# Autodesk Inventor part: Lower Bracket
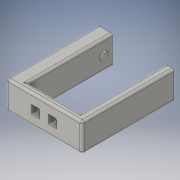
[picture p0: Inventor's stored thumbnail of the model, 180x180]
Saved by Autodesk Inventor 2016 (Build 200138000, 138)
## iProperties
Created: 2015-09
Part Number: Lower Bracket
Material: Generic
Document SubType Name: Modeling
Designer: ChombaW
Density: 1 g/cm^3
Appearance: Default
Author: ChombaW
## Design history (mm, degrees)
sketch "Sketch1"
  geometry: L1 (27.165, 10.16)-(-27.165, 10.16); L2 (-27.165, 10.16)-(-27.165, -10.16); L3 (-27.165, -10.16)-(27.165, -10.16); L4 (27.165, -10.16)-(27.165, 10.16); L5 (27.165, 10.16)-(-27.165, -10.16); L6 (-27.165, 10.16)-(27.165, -10.16); 1 further point
  constraints: 12 end point, 2 midpoint, 2 parallel, 1 horizontal, 1 perpendicular
  dimensions: "d0" = 54.3306 distance of L3.end L2.end; "d1" = 20.32 distance of L2.end L1.end
extrude "Extrusion1" new body sketch "Sketch1" distance "d2" = 5.08; taper "d3" = 0 deg
sketch "Sketch2"
  geometry: L1 (-3.048, 3.048)-(-9.144, 3.048); L2 (-9.144, 3.048)-(-9.144, -3.048); L3 (-9.144, -3.048)-(-3.048, -3.048); L4 (-3.048, -3.048)-(-3.048, 3.048); L5 (-3.048, 3.048)-(-9.144, -3.048); L6 (-9.144, 3.048)-(-3.048, -3.048); L7 (9.144, -3.048)-(3.048, -3.048); L8 (3.048, -3.048)-(3.048, 3.048); L9 (3.048, 3.048)-(9.144, 3.048); L10 (9.144, 3.048)-(9.144, -3.048); L11 (9.144, -3.048)-(3.048, 3.048); L12 (3.048, -3.048)-(9.144, 3.048); L13 (27.165, -10.16)-(27.165, 10.16) reference; L14 (-27.165, 10.16)-(-27.165, -10.16) reference; 3 further points
  constraints: 24 end point, 4 midpoint, 4 parallel, 2 horizontal, 2 perpendicular
  dimensions: "d4" = 6.096 distance of L3.end L2.end; "d5" = 6.096 distance of L2.end L1.end; "d6" = 6.096 distance of L8.end L9.end; "d7" = 6.096 distance of L7.end L8.end; "d8" = 12.192 distance of L8.end L1.end; "d9" = 18.0213 distance from line of L13 L9.end; "d10" = 18.0213 distance from line of L14 L2.end
extrude "Extrusion2" cut sketch "Sketch2" distance "d11" = 5.08; taper "d12" = 0 deg
sketch "Sketch3"
  geometry: L1 (27.165, 10.16)-(16.65, 10.16); L2 (16.65, 10.16)-(16.65, -10.16); L3 (16.65, -10.16)-(27.165, -10.16); L4 (27.165, -10.16)-(27.165, 10.16); L5 (27.165, 10.16)-(16.65, -10.16); L6 (16.65, 10.16)-(27.165, -10.16); L7 (27.165, -10.16)-(27.165, 10.16) reference; L8 (-21.069, 10.16)-(-27.165, 10.16); L9 (-27.165, 10.16)-(-27.165, -10.16); L10 (-27.165, -10.16)-(-21.069, -10.16); L11 (-21.069, -10.16)-(-21.069, 10.16); L12 (-21.069, 10.16)-(-27.165, -10.16); L13 (-27.165, 10.16)-(-21.069, -10.16); L14 (-27.165, 10.16)-(-27.165, -10.16) reference; 3 further points
  constraints: 24 end point, 4 midpoint, 4 parallel, 2 horizontal, 2 perpendicular
  dimensions: "d13" = 10.5156 distance of L3.end L2.end; "d14" = 20.32 distance of L2.end L1.end; "d15" = 0 distance from line of L7 L1.start; "d16" = 6.096 distance of L10.end L9.end; "d17" = 20.32 distance of L9.end L8.end; "d18" = 0 distance from line of L14 L8.end
extrude "Extrusion3" join sketch "Sketch3" distance "d19" = 60.4266; taper "d20" = 0 deg
sketch "Sketch4"
  geometry: L1 (-51.51, 14.427)-(-40.457, 14.427); L2 (-40.457, 14.427)-(-27.428, 12.82); L3 (-27.428, 7.5)-(-40.457, 5.893); L4 (-40.457, 5.893)-(-53.372, 5.439); L5 (-53.372, 5.439)-(-65.507, 5.439); L6 (-65.507, 0)-(-65.507, 20.32) reference; L7 (-53.372, 14.881)-(-65.507, 14.881); A1 r 4.724 centre (-53.538, 10.16) between (-51.51, 14.427) and (-53.372, 5.439); A2 r 4.267 centre (-40.457, 10.16) between (-40.457, 14.427) and (-40.457, 5.893); A3 r 2.68 centre (-27.757, 10.16) between (-27.428, 12.82) and (-27.428, 7.5); 1 further point
  constraints: 12 end point, 7 point on circle, 3 centre point, 3 tangent, 2 point on line, 1 horizontal, 1 parallel
  dimensions: "d21" = 9.4488 diameter of A1; "d22" = 8.5344 diameter of A2; "d23" = 5.3594 diameter of A3; "d24" = 13.081 distance of A2.centre A1.centre; "d25" = 12.7 distance of A3.centre A2.centre
extrude "Extrusion4" cut sketch "Sketch4" distance "d26" = 9.398; taper "d27" = 0 deg
sketch "Sketch5"
  geometry: L1 (-65.507, 14.881)-(-53.372, 14.881) reference; L2 (-53.372, 5.439)-(-65.507, 5.439) reference; C1 r 3.023 at (-59.006, 10.157); 1 further point
  constraints: 1 centre point
  dimensions: "d28" = 6.0452 diameter of C1; "d29" = 4.7244 distance from line of L1 C1.centre; "d30" = 4.71856 distance from line of L2 C1.centre (derived)
extrude "Extrusion5" cut sketch "Sketch5" distance "d31" = 4.4196; taper "d32" = 0 deg
fillet "Fillet1" dims "d33" = 1.5875
fillet "Fillet2" dims "d34" = 1.5875
fillet "Fillet3" dims "d35" = 1.5875
fillet "Fillet4" dims "d36" = 1.5875
fillet "Fillet5" dims "d37" = 1.5875
body "Solid1"
